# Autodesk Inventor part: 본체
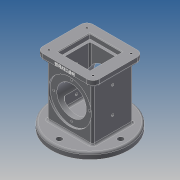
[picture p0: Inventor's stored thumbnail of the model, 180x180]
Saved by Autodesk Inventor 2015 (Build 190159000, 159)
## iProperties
Created: 2018-10
Part Number: 본체
Material: 일반
Document SubType Name: Modeling
Designer: user
Density: 1 g/cm^3
Appearance: 기본값
Author: user
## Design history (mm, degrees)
sketch "스케치1"
  geometry: C1 r 62.5 at (0, 0); 1 further point
  constraints: 1 centre point, 1 coincident
  dimensions: "d0" = 125 diameter of C1
extrude "돌출1" new body sketch "스케치1" distance "d1" = 10; taper "d2" = 0 deg
sketch "스케치2"
  geometry: L1 (-37, -33)-(37, -33); L2 (37, -33)-(37, 33); L3 (37, 33)-(-37, 33); L4 (-37, 33)-(-37, -33); L5 (-37, -33)-(37, 33); L6 (37, -33)-(-37, 33); C1 r 62.5 at (0, 0) reference
  constraints: 12 end point, 2 midpoint, 2 parallel, 1 horizontal, 1 perpendicular
  dimensions: "d3" = 74 distance of L3.end L2.end; "d4" = 66 distance of L2.end L1.end
extrude "돌출2" join sketch "스케치2" distance "d5" = 88; taper "d6" = 0 deg
sketch "스케치3"
  geometry: L1 (46, -41)-(-46, -41); L2 (-46, -41)-(-46, 41); L3 (-46, 41)-(46, 41); L4 (46, 41)-(46, -41); L5 (46, -41)-(-46, 41); L6 (-46, -41)-(46, 41); 1 further point
  constraints: 12 end point, 2 midpoint, 2 parallel, 1 horizontal, 1 perpendicular
  dimensions: "d7" = 92 distance of L2.end L3.end; "d8" = 82 distance of L3.end L1.start
extrude "돌출3" join sketch "스케치3" distance "d9" = 10; taper "d10" = 0 deg
sketch "스케치4"
  geometry: L1 (-26, -26)-(26, -26); L2 (26, -26)-(26, 26); L3 (26, 26)-(-26, 26); L4 (-26, 26)-(-26, -26); L5 (-26, -26)-(26, 26); L6 (26, -26)-(-26, 26); 1 further point
  constraints: 12 end point, 2 midpoint, 2 parallel, 1 horizontal, 1 perpendicular
  dimensions: "d11" = 52 distance of L3.end L2.end; "d12" = 52 distance of L2.end L1.end
extrude "돌출4" cut sketch "스케치4" distance "d13" = 8; taper "d14" = 0 deg
sketch "스케치5"
  geometry: L1 (-25.5, -10)-(99.5, -10) reference; C1 r 35 at (37, 44); 1 further point
  constraints: 1 centre point
  dimensions: "d15" = 54 distance from line of L1 C1.centre; "d16" = 70 diameter of C1
extrude "돌출5" cut sketch "스케치5" distance "d17" = 3; taper "d18" = 0 deg
sketch "스케치6"
  geometry: C1 r 35 at (0, 0) reference; C2 r 24 at (0, 0); 1 further point
  constraints: 1 centre point, 1 coincident
  dimensions: "d19" = 48 diameter of C2
extrude "돌출6" cut sketch "스케치6" stored distance "d20" = 3; taper "d21" = 0 deg
sketch "스케치7"
  geometry: L1 (-22, -22)-(22, -22); L2 (22, -22)-(22, 22); L3 (22, 22)-(-22, 22); L4 (-22, 22)-(-22, -22); L5 (-22, -22)-(22, 22); L6 (22, -22)-(-22, 22); 1 further point
  constraints: 12 end point, 2 midpoint, 2 parallel, 1 horizontal, 1 perpendicular
  dimensions: "d22" = 44 distance of L3.end L2.end; "d23" = 44 distance of L2.end L1.end
extrude "돌출7" cut sketch "스케치7" distance "d24" = 74; taper "d25" = 0 deg
chamfer "모따기1" distance "d26" = 1; stored, may be unused: second distance "d27" = 2, angle "d28" = 45 deg
sketch "스케치9"
  geometry: C1 r 62.5 at (0, 0) reference; C2 r 28 at (0, 0)
  constraints: 1 centre point, 1 coincident
  dimensions: "d29" = 56 diameter of C2
extrude "돌출8" cut sketch "스케치9" distance "d30" = 18; taper "d31" = -20 deg
sketch "스케치10"
  geometry: L1 (10, 33)-(-27, 33); L2 (-27, 33)-(-70, 33); 2 further points
  constraints: 4 end point, 2 coincident, 1 horizontal, 1 point on line
  dimensions: "d32" = 37 distance of L1.start L1.end; "d33" = 43 distance of L1.end L2.end
hole "구멍1" sketch "스케치10" at (-70, 33), (-27, 33) diameter "d34" = 4.134; stored, may be unused: countersink angle "d38" = 90 deg, drill point angle "d40" = 118 deg; dims "d35" = 10, "d36" = 4, "d37" = 2, "d39" = 14.2
sketch "스케치11"
  geometry: C1 r 24 at (0, 0) reference; C2 r 35 at (0, 0) reference; A1 r 29 centre (0, 0) between (0, 29) and (-29, 0); 3 further points
  constraints: 4 point on circle, 2 horizontal alignment, 2 vertical alignment, 1 centre point, 1 coincident
  dimensions: "d41" = 58 diameter of A1
hole "구멍2" sketch "스케치11" at (0, 29), (-29, 0), (0, -29), (29, 0) diameter "d42" = 3.242; stored, may be unused: countersink angle "d46" = 90 deg, drill point angle "d48" = 118 deg; dims "d43" = 4, "d44" = 4, "d45" = 2, "d47" = 6
sketch "스케치12"
  geometry: C1 r 62.5 at (0, 0) reference; A1 r 50 centre (0, 0) between (0, 50) and (-50, 0); 2 further points
  constraints: 4 point on circle, 2 horizontal alignment, 2 vertical alignment, 1 centre point, 1 coincident
  dimensions: "d49" = 100 diameter of A1
hole "구멍3" sketch "스케치12" at (0, 50), (-50, 0), (0, -50), (50, 0) diameter "d50" = 9; stored, may be unused: countersink angle "d54" = 90 deg, drill point angle "d56" = 118 deg; dims "d51" = 4, "d52" = 4, "d53" = 2, "d55" = 6
sketch "스케치13"
  geometry: L1 (36, -31)-(-36, -31); L2 (-36, -31)-(-36, 31); L3 (-36, 31)-(36, 31); L4 (36, 31)-(36, -31); L5 (36, -31)-(-36, 31); L6 (-36, -31)-(36, 31); 5 further points
  constraints: 12 end point, 4 coincident, 2 midpoint, 2 parallel, 1 horizontal, 1 perpendicular
  dimensions: "d57" = 72 distance of L2.end L3.end; "d58" = 62 distance of L3.end L1.start
hole "구멍4" sketch "스케치13" at (-36, 31), (-36, -31), (36, -31), (36, 31) diameter "d59" = 3.242; stored, may be unused: countersink angle "d63" = 90 deg, drill point angle "d65" = 118 deg; dims "d60" = 4, "d61" = 4, "d62" = 2, "d64" = 6
fillet "모깎기1" dims "d66" = 10
fillet "모깎기2" dims "d67" = 3
fillet "모깎기3" dims "d68" = 3
fillet "모깎기4" dims "d69" = 3
fillet "모깎기5" dims "d70" = 3
fillet "모깎기6" dims "d71" = 3
fillet "모깎기7" dims "d72" = 3
fillet "모깎기8" dims "d73" = 3
fillet "모깎기9" dims "d74" = 3
sketch "스케치14"
  geometry: L1 (0, 0)-(72, 0) reference; L2 (-10, 0)-(-10, -7) reference; 2 further points
  constraints: 1 other
  dimensions: "d75" = 46 distance from line of point (36, -4) L2; "d76" = 4 distance from line of L1 point (36, -4)
feature "엠보싱1" sketch "스케치14" dims "d2" = 0, "d10" = 0, "d77" = 0.5, "d78" = 0
node "솔리드1"
mirror "대칭1"
mirror "대칭2"
